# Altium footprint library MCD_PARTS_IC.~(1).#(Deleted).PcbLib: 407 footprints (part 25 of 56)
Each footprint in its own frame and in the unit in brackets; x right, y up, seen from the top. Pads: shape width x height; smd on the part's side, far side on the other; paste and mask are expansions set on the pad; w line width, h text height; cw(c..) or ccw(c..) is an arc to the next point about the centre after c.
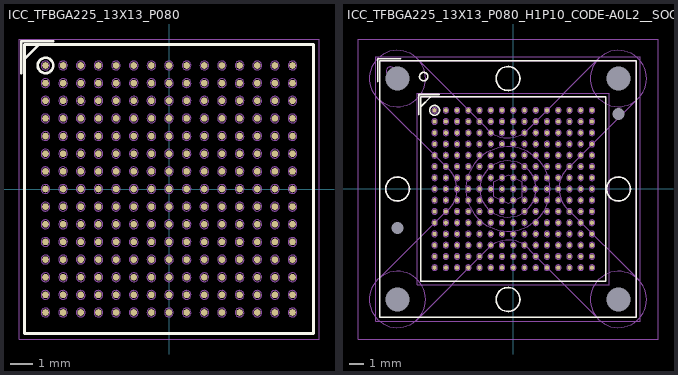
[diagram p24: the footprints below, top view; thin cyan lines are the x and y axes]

## ICC_TFBGA225_13X13_P080 [mm] "MCD-04287"
height 1.2
pads (225):
  round 0.3 smd mask+0.05: A1(-5.6,5.6) A2(-4.8,5.6) A3(-4,5.6) A4(-3.2,5.6) A5(-2.4,5.6) A6(-1.6,5.6) A7(-0.8,5.6) A8(0,5.6) A9(0.8,5.6) A10(1.6,5.6) A11(2.4,5.6) A12(3.2,5.6) A13(4,5.6) A14(4.8,5.6) A15(5.6,5.6) B1(-5.6,4.8) B2(-4.8,4.8) B3(-4,4.8) B4(-3.2,4.8) B5(-2.4,4.8) B6(-1.6,4.8) B7(-0.8,4.8) B8(0,4.8) B9(0.8,4.8) B10(1.6,4.8) B11(2.4,4.8) B12(3.2,4.8) B13(4,4.8) B14(4.8,4.8) B15(5.6,4.8) C1(-5.6,4) C2(-4.8,4) C3(-4,4) C4(-3.2,4) C5(-2.4,4) C6(-1.6,4) C7(-0.8,4) C8(0,4) C9(0.8,4) C10(1.6,4) C11(2.4,4) C12(3.2,4) C13(4,4) C14(4.8,4) C15(5.6,4) D1(-5.6,3.2) D2(-4.8,3.2) D3(-4,3.2) D4(-3.2,3.2) D5(-2.4,3.2) D6(-1.6,3.2) D7(-0.8,3.2) D8(0,3.2) D9(0.8,3.2) D10(1.6,3.2) D11(2.4,3.2) D12(3.2,3.2) D13(4,3.2) D14(4.8,3.2) D15(5.6,3.2) E1(-5.6,2.4) E2(-4.8,2.4) E3(-4,2.4) E4(-3.2,2.4) E5(-2.4,2.4) E6(-1.6,2.4) E7(-0.8,2.4) E8(0,2.4) E9(0.8,2.4) E10(1.6,2.4) E11(2.4,2.4) E12(3.2,2.4) E13(4,2.4) E14(4.8,2.4) E15(5.6,2.4) F1(-5.6,1.6) F2(-4.8,1.6) F3(-4,1.6) F4(-3.2,1.6) F5(-2.4,1.6) F6(-1.6,1.6) F7(-0.8,1.6) F8(0,1.6) F9(0.8,1.6) F10(1.6,1.6) F11(2.4,1.6) F12(3.2,1.6) F13(4,1.6) F14(4.8,1.6) F15(5.6,1.6) G1(-5.6,0.8) G2(-4.8,0.8) G3(-4,0.8) G4(-3.2,0.8) G5(-2.4,0.8) G6(-1.6,0.8) G7(-0.8,0.8) G8(0,0.8) G9(0.8,0.8) G10(1.6,0.8) G11(2.4,0.8) G12(3.2,0.8) G13(4,0.8) G14(4.8,0.8) G15(5.6,0.8) H1(-5.6,0) H2(-4.8,0) H3(-4,0) H4(-3.2,0) H5(-2.4,0) H6(-1.6,0) H7(-0.8,0) H8(0,0) H9(0.8,0) H10(1.6,0) H11(2.4,0) H12(3.2,0) H13(4,0) H14(4.8,0) H15(5.6,0) J1(-5.6,-0.8) J2(-4.8,-0.8) J3(-4,-0.8) J4(-3.2,-0.8) J5(-2.4,-0.8) J6(-1.6,-0.8) J7(-0.8,-0.8) J8(0,-0.8) J9(0.8,-0.8) J10(1.6,-0.8) J11(2.4,-0.8) J12(3.2,-0.8) J13(4,-0.8) J14(4.8,-0.8) J15(5.6,-0.8) K1(-5.6,-1.6) K2(-4.8,-1.6) K3(-4,-1.6) K4(-3.2,-1.6) K5(-2.4,-1.6) K6(-1.6,-1.6) K7(-0.8,-1.6) K8(0,-1.6) K9(0.8,-1.6) K10(1.6,-1.6) K11(2.4,-1.6) K12(3.2,-1.6) K13(4,-1.6) K14(4.8,-1.6) K15(5.6,-1.6) L1(-5.6,-2.4) L2(-4.8,-2.4) L3(-4,-2.4) L4(-3.2,-2.4) L5(-2.4,-2.4) L6(-1.6,-2.4) L7(-0.8,-2.4) L8(0,-2.4) L9(0.8,-2.4) L10(1.6,-2.4) L11(2.4,-2.4) L12(3.2,-2.4) L13(4,-2.4) L14(4.8,-2.4) L15(5.6,-2.4) M1(-5.6,-3.2) M2(-4.8,-3.2) M3(-4,-3.2) M4(-3.2,-3.2) M5(-2.4,-3.2) M6(-1.6,-3.2) M7(-0.8,-3.2) M8(0,-3.2) M9(0.8,-3.2) M10(1.6,-3.2) M11(2.4,-3.2) M12(3.2,-3.2) M13(4,-3.2) M14(4.8,-3.2) M15(5.6,-3.2) N1(-5.6,-4) N2(-4.8,-4) N3(-4,-4) N4(-3.2,-4) N5(-2.4,-4) N6(-1.6,-4) N7(-0.8,-4) N8(0,-4) N9(0.8,-4) N10(1.6,-4) N11(2.4,-4) N12(3.2,-4) N13(4,-4) N14(4.8,-4) N15(5.6,-4) P1(-5.6,-4.8) P2(-4.8,-4.8) P3(-4,-4.8) P4(-3.2,-4.8) P5(-2.4,-4.8) P6(-1.6,-4.8) P7(-0.8,-4.8) P8(0,-4.8) P9(0.8,-4.8) P10(1.6,-4.8) P11(2.4,-4.8) P12(3.2,-4.8) P13(4,-4.8) P14(4.8,-4.8) P15(5.6,-4.8) R1(-5.6,-5.6) R2(-4.8,-5.6) R3(-4,-5.6) R4(-3.2,-5.6) R5(-2.4,-5.6) R6(-1.6,-5.6) R7(-0.8,-5.6) R8(0,-5.6) R9(0.8,-5.6) R10(1.6,-5.6) R11(2.4,-5.6) R12(3.2,-5.6) R13(4,-5.6) R14(4.8,-5.6) R15(5.6,-5.6)
Top Overlay:
  circle w0.12: c-5.6,5.6 r0.35
  lines w0.12: -6.7,5.25 -6.7,6.7 -5.25,6.7 ; -6.55,5.895 -5.895,6.55 ; -6.55,-6.55 6.55,-6.55 6.55,6.55 -6.55,6.55 -6.55,-6.55
M14-Top Assembly:
  drawing of 229 lines, arcs and shapes, not listed
  text "'.Designator'" at 0,0 h0.75
  text "A1" at -5.85,5.425 h0.4
M16-Top Courtyard:
  lines w0.01: -6.8,-6.8 6.8,-6.8 6.8,6.8 -6.8,6.8 -6.8,-6.8
3D body: height 0.36, standoff -0.04, extent 5.401,5.403 5.8,5.797
3D body: height 1.2, standoff 0.3, extent -6.55,-6.55 6.55,6.55
3D body: height 0.36, standoff -0.04, extent 4.601,5.403 5,5.797
3D body: height 0.36, standoff -0.04, extent 3.801,5.403 4.2,5.797
3D body: height 0.36, standoff -0.04, extent 3.001,5.403 3.4,5.797
3D body: height 0.36, standoff -0.04, extent 2.201,5.403 2.6,5.797
3D body: height 0.36, standoff -0.04, extent -1.799,5.403 -1.4,5.797
3D body: height 0.36, standoff -0.04, extent -0.999,5.403 -0.6,5.797
3D body: height 0.36, standoff -0.04, extent -0.199,5.403 0.2,5.797
3D body: height 0.36, standoff -0.04, extent 0.601,5.403 1,5.797
3D body: height 0.36, standoff -0.04, extent 1.401,5.403 1.8,5.797
3D body: height 0.36, standoff -0.04, extent -5.799,5.403 -5.4,5.797
3D body: height 0.36, standoff -0.04, extent -4.999,5.403 -4.6,5.797
3D body: height 0.36, standoff -0.04, extent -4.199,5.403 -3.8,5.797
3D body: height 0.36, standoff -0.04, extent -3.399,5.403 -3,5.797
3D body: height 0.36, standoff -0.04, extent -2.599,5.403 -2.2,5.797
3D body: height 0.36, standoff -0.04, extent -2.599,4.603 -2.2,4.997
3D body: height 0.36, standoff -0.04, extent -3.399,4.603 -3,4.997
3D body: height 0.36, standoff -0.04, extent -4.199,4.603 -3.8,4.997
3D body: height 0.36, standoff -0.04, extent -4.999,4.603 -4.6,4.997
3D body: height 0.36, standoff -0.04, extent -5.799,4.603 -5.4,4.997
3D body: height 0.36, standoff -0.04, extent 1.401,4.603 1.8,4.997
3D body: height 0.36, standoff -0.04, extent 0.601,4.603 1,4.997
3D body: height 0.36, standoff -0.04, extent -0.199,4.603 0.2,4.997
3D body: height 0.36, standoff -0.04, extent -0.999,4.603 -0.6,4.997
3D body: height 0.36, standoff -0.04, extent -1.799,4.603 -1.4,4.997
3D body: height 0.36, standoff -0.04, extent 2.201,4.603 2.6,4.997
3D body: height 0.36, standoff -0.04, extent 3.001,4.603 3.4,4.997
3D body: height 0.36, standoff -0.04, extent 3.801,4.603 4.2,4.997
3D body: height 0.36, standoff -0.04, extent 4.601,4.603 5,4.997
3D body: height 0.36, standoff -0.04, extent 5.401,4.603 5.8,4.997
3D body: height 0.36, standoff -0.04, extent -2.599,3.803 -2.2,4.197
3D body: height 0.36, standoff -0.04, extent -3.399,3.803 -3,4.197
3D body: height 0.36, standoff -0.04, extent -4.199,3.803 -3.8,4.197
3D body: height 0.36, standoff -0.04, extent -4.999,3.803 -4.6,4.197
3D body: height 0.36, standoff -0.04, extent -5.799,3.803 -5.4,4.197
3D body: height 0.36, standoff -0.04, extent 1.401,3.803 1.8,4.197
3D body: height 0.36, standoff -0.04, extent 0.601,3.803 1,4.197
3D body: height 0.36, standoff -0.04, extent -0.199,3.803 0.2,4.197
3D body: height 0.36, standoff -0.04, extent -0.999,3.803 -0.6,4.197
3D body: height 0.36, standoff -0.04, extent -1.799,3.803 -1.4,4.197
3D body: height 0.36, standoff -0.04, extent 2.201,3.803 2.6,4.197
3D body: height 0.36, standoff -0.04, extent 3.001,3.803 3.4,4.197
3D body: height 0.36, standoff -0.04, extent 3.801,3.803 4.2,4.197
3D body: height 0.36, standoff -0.04, extent 4.601,3.803 5,4.197
3D body: height 0.36, standoff -0.04, extent 5.401,3.803 5.8,4.197
3D body: height 0.36, standoff -0.04, extent -2.599,3.003 -2.2,3.397
3D body: height 0.36, standoff -0.04, extent -3.399,3.003 -3,3.397
3D body: height 0.36, standoff -0.04, extent -4.199,3.003 -3.8,3.397
3D body: height 0.36, standoff -0.04, extent -4.999,3.003 -4.6,3.397
3D body: height 0.36, standoff -0.04, extent -5.799,3.003 -5.4,3.397
3D body: height 0.36, standoff -0.04, extent 1.401,3.003 1.8,3.397
3D body: height 0.36, standoff -0.04, extent 0.601,3.003 1,3.397
3D body: height 0.36, standoff -0.04, extent -0.199,3.003 0.2,3.397
3D body: height 0.36, standoff -0.04, extent -0.999,3.003 -0.6,3.397
3D body: height 0.36, standoff -0.04, extent -1.799,3.003 -1.4,3.397
3D body: height 0.36, standoff -0.04, extent 2.201,3.003 2.6,3.397
3D body: height 0.36, standoff -0.04, extent 3.001,3.003 3.4,3.397
3D body: height 0.36, standoff -0.04, extent 3.801,3.003 4.2,3.397
3D body: height 0.36, standoff -0.04, extent 4.601,3.003 5,3.397
3D body: height 0.36, standoff -0.04, extent 5.401,3.003 5.8,3.397
3D body: height 0.36, standoff -0.04, extent -2.599,2.203 -2.2,2.597
3D body: height 0.36, standoff -0.04, extent -3.399,2.203 -3,2.597
3D body: height 0.36, standoff -0.04, extent -4.199,2.203 -3.8,2.597
3D body: height 0.36, standoff -0.04, extent -4.999,2.203 -4.6,2.597
3D body: height 0.36, standoff -0.04, extent -5.799,2.203 -5.4,2.597
3D body: height 0.36, standoff -0.04, extent 1.401,2.203 1.8,2.597
3D body: height 0.36, standoff -0.04, extent 0.601,2.203 1,2.597
3D body: height 0.36, standoff -0.04, extent -0.199,2.203 0.2,2.597
3D body: height 0.36, standoff -0.04, extent -0.999,2.203 -0.6,2.597
3D body: height 0.36, standoff -0.04, extent -1.799,2.203 -1.4,2.597
3D body: height 0.36, standoff -0.04, extent 2.201,2.203 2.6,2.597
3D body: height 0.36, standoff -0.04, extent 3.001,2.203 3.4,2.597
3D body: height 0.36, standoff -0.04, extent 3.801,2.203 4.2,2.597
3D body: height 0.36, standoff -0.04, extent 4.601,2.203 5,2.597
3D body: height 0.36, standoff -0.04, extent 5.401,2.203 5.8,2.597
3D body: height 0.36, standoff -0.04, extent -2.599,1.403 -2.2,1.797
3D body: height 0.36, standoff -0.04, extent -3.399,1.403 -3,1.797
3D body: height 0.36, standoff -0.04, extent -4.199,1.403 -3.8,1.797
3D body: height 0.36, standoff -0.04, extent -4.999,1.403 -4.6,1.797
3D body: height 0.36, standoff -0.04, extent -5.799,1.403 -5.4,1.797
3D body: height 0.36, standoff -0.04, extent 1.401,1.403 1.8,1.797
3D body: height 0.36, standoff -0.04, extent 0.601,1.403 1,1.797
3D body: height 0.36, standoff -0.04, extent -0.199,1.403 0.2,1.797
3D body: height 0.36, standoff -0.04, extent -0.999,1.403 -0.6,1.797
3D body: height 0.36, standoff -0.04, extent -1.799,1.403 -1.4,1.797
3D body: height 0.36, standoff -0.04, extent 2.201,1.403 2.6,1.797
3D body: height 0.36, standoff -0.04, extent 3.001,1.403 3.4,1.797
3D body: height 0.36, standoff -0.04, extent 3.801,1.403 4.2,1.797
3D body: height 0.36, standoff -0.04, extent 4.601,1.403 5,1.797
3D body: height 0.36, standoff -0.04, extent 5.401,1.403 5.8,1.797
3D body: height 0.36, standoff -0.04, extent -2.599,0.603 -2.2,0.997
3D body: height 0.36, standoff -0.04, extent -3.399,0.603 -3,0.997
3D body: height 0.36, standoff -0.04, extent -4.199,0.603 -3.8,0.997
3D body: height 0.36, standoff -0.04, extent -4.999,0.603 -4.6,0.997
3D body: height 0.36, standoff -0.04, extent -5.799,0.603 -5.4,0.997
3D body: height 0.36, standoff -0.04, extent 1.401,0.603 1.8,0.997
3D body: height 0.36, standoff -0.04, extent 0.601,0.603 1,0.997
3D body: height 0.36, standoff -0.04, extent -0.199,0.603 0.2,0.997
3D body: height 0.36, standoff -0.04, extent -0.999,0.603 -0.6,0.997
3D body: height 0.36, standoff -0.04, extent -1.799,0.603 -1.4,0.997
3D body: height 0.36, standoff -0.04, extent 2.201,0.603 2.6,0.997
3D body: height 0.36, standoff -0.04, extent 3.001,0.603 3.4,0.997
3D body: height 0.36, standoff -0.04, extent 3.801,0.603 4.2,0.997
3D body: height 0.36, standoff -0.04, extent 4.601,0.603 5,0.997
3D body: height 0.36, standoff -0.04, extent 5.401,0.603 5.8,0.997
3D body: height 0.36, standoff -0.04, extent -2.599,-0.197 -2.2,0.197
3D body: height 0.36, standoff -0.04, extent -3.399,-0.197 -3,0.197
3D body: height 0.36, standoff -0.04, extent -4.199,-0.197 -3.8,0.197
3D body: height 0.36, standoff -0.04, extent -4.999,-0.197 -4.6,0.197
3D body: height 0.36, standoff -0.04, extent -5.799,-0.197 -5.4,0.197
3D body: height 0.36, standoff -0.04, extent 1.401,-0.197 1.8,0.197
3D body: height 0.36, standoff -0.04, extent 0.601,-0.197 1,0.197
3D body: height 0.36, standoff -0.04, extent -0.199,-0.197 0.2,0.197
3D body: height 0.36, standoff -0.04, extent -0.999,-0.197 -0.6,0.197
3D body: height 0.36, standoff -0.04, extent -1.799,-0.197 -1.4,0.197
3D body: height 0.36, standoff -0.04, extent 2.201,-0.197 2.6,0.197
3D body: height 0.36, standoff -0.04, extent 3.001,-0.197 3.4,0.197
3D body: height 0.36, standoff -0.04, extent 3.801,-0.197 4.2,0.197
3D body: height 0.36, standoff -0.04, extent 4.601,-0.197 5,0.197
3D body: height 0.36, standoff -0.04, extent 5.401,-0.197 5.8,0.197
3D body: height 0.36, standoff -0.04, extent -2.599,-0.997 -2.2,-0.603
3D body: height 0.36, standoff -0.04, extent -3.399,-0.997 -3,-0.603
3D body: height 0.36, standoff -0.04, extent -4.199,-0.997 -3.8,-0.603
3D body: height 0.36, standoff -0.04, extent -4.999,-0.997 -4.6,-0.603
3D body: height 0.36, standoff -0.04, extent -5.799,-0.997 -5.4,-0.603
3D body: height 0.36, standoff -0.04, extent 1.401,-0.997 1.8,-0.603
3D body: height 0.36, standoff -0.04, extent 0.601,-0.997 1,-0.603
3D body: height 0.36, standoff -0.04, extent -0.199,-0.997 0.2,-0.603
3D body: height 0.36, standoff -0.04, extent -0.999,-0.997 -0.6,-0.603
3D body: height 0.36, standoff -0.04, extent -1.799,-0.997 -1.4,-0.603
3D body: height 0.36, standoff -0.04, extent 2.201,-0.997 2.6,-0.603
3D body: height 0.36, standoff -0.04, extent 3.001,-0.997 3.4,-0.603
3D body: height 0.36, standoff -0.04, extent 3.801,-0.997 4.2,-0.603
3D body: height 0.36, standoff -0.04, extent 4.601,-0.997 5,-0.603
3D body: height 0.36, standoff -0.04, extent 5.401,-0.997 5.8,-0.603
3D body: height 0.36, standoff -0.04, extent -2.599,-1.797 -2.2,-1.403
3D body: height 0.36, standoff -0.04, extent -3.399,-1.797 -3,-1.403
3D body: height 0.36, standoff -0.04, extent -4.199,-1.797 -3.8,-1.403
3D body: height 0.36, standoff -0.04, extent -4.999,-1.797 -4.6,-1.403
3D body: height 0.36, standoff -0.04, extent -5.799,-1.797 -5.4,-1.403
3D body: height 0.36, standoff -0.04, extent 1.401,-1.797 1.8,-1.403
3D body: height 0.36, standoff -0.04, extent 0.601,-1.797 1,-1.403
3D body: height 0.36, standoff -0.04, extent -0.199,-1.797 0.2,-1.403
3D body: height 0.36, standoff -0.04, extent -0.999,-1.797 -0.6,-1.403
3D body: height 0.36, standoff -0.04, extent -1.799,-1.797 -1.4,-1.403
3D body: height 0.36, standoff -0.04, extent 2.201,-1.797 2.6,-1.403
3D body: height 0.36, standoff -0.04, extent 3.001,-1.797 3.4,-1.403
3D body: height 0.36, standoff -0.04, extent 3.801,-1.797 4.2,-1.403
3D body: height 0.36, standoff -0.04, extent 4.601,-1.797 5,-1.403
3D body: height 0.36, standoff -0.04, extent 5.401,-1.797 5.8,-1.403
3D body: height 0.36, standoff -0.04, extent -2.599,-2.597 -2.2,-2.203
3D body: height 0.36, standoff -0.04, extent -3.399,-2.597 -3,-2.203
3D body: height 0.36, standoff -0.04, extent -4.199,-2.597 -3.8,-2.203
3D body: height 0.36, standoff -0.04, extent -4.999,-2.597 -4.6,-2.203
3D body: height 0.36, standoff -0.04, extent -5.799,-2.597 -5.4,-2.203
3D body: height 0.36, standoff -0.04, extent 1.401,-2.597 1.8,-2.203
3D body: height 0.36, standoff -0.04, extent 0.601,-2.597 1,-2.203
3D body: height 0.36, standoff -0.04, extent -0.199,-2.597 0.2,-2.203
3D body: height 0.36, standoff -0.04, extent -0.999,-2.597 -0.6,-2.203
3D body: height 0.36, standoff -0.04, extent -1.799,-2.597 -1.4,-2.203
3D body: height 0.36, standoff -0.04, extent 2.201,-2.597 2.6,-2.203
3D body: height 0.36, standoff -0.04, extent 3.001,-2.597 3.4,-2.203
3D body: height 0.36, standoff -0.04, extent 3.801,-2.597 4.2,-2.203
3D body: height 0.36, standoff -0.04, extent 4.601,-2.597 5,-2.203
3D body: height 0.36, standoff -0.04, extent 5.401,-2.597 5.8,-2.203
3D body: height 0.36, standoff -0.04, extent -2.599,-3.397 -2.2,-3.003
3D body: height 0.36, standoff -0.04, extent -3.399,-3.397 -3,-3.003
3D body: height 0.36, standoff -0.04, extent -4.199,-3.397 -3.8,-3.003
3D body: height 0.36, standoff -0.04, extent -4.999,-3.397 -4.6,-3.003
3D body: height 0.36, standoff -0.04, extent -5.799,-3.397 -5.4,-3.003
3D body: height 0.36, standoff -0.04, extent 1.401,-3.397 1.8,-3.003
3D body: height 0.36, standoff -0.04, extent 0.601,-3.397 1,-3.003
3D body: height 0.36, standoff -0.04, extent -0.199,-3.397 0.2,-3.003
3D body: height 0.36, standoff -0.04, extent -0.999,-3.397 -0.6,-3.003
3D body: height 0.36, standoff -0.04, extent -1.799,-3.397 -1.4,-3.003
3D body: height 0.36, standoff -0.04, extent 2.201,-3.397 2.6,-3.003
3D body: height 0.36, standoff -0.04, extent 3.001,-3.397 3.4,-3.003
3D body: height 0.36, standoff -0.04, extent 3.801,-3.397 4.2,-3.003
3D body: height 0.36, standoff -0.04, extent 4.601,-3.397 5,-3.003
3D body: height 0.36, standoff -0.04, extent 5.401,-3.397 5.8,-3.003
3D body: height 0.36, standoff -0.04, extent -2.599,-4.197 -2.2,-3.803
3D body: height 0.36, standoff -0.04, extent -3.399,-4.197 -3,-3.803
3D body: height 0.36, standoff -0.04, extent -4.199,-4.197 -3.8,-3.803
3D body: height 0.36, standoff -0.04, extent -4.999,-4.197 -4.6,-3.803
3D body: height 0.36, standoff -0.04, extent -5.799,-4.197 -5.4,-3.803
3D body: height 0.36, standoff -0.04, extent 1.401,-4.197 1.8,-3.803
3D body: height 0.36, standoff -0.04, extent 0.601,-4.197 1,-3.803
3D body: height 0.36, standoff -0.04, extent -0.199,-4.197 0.2,-3.803
3D body: height 0.36, standoff -0.04, extent -0.999,-4.197 -0.6,-3.803
3D body: height 0.36, standoff -0.04, extent -1.799,-4.197 -1.4,-3.803
3D body: height 0.36, standoff -0.04, extent 2.201,-4.197 2.6,-3.803
3D body: height 0.36, standoff -0.04, extent 3.001,-4.197 3.4,-3.803
3D body: height 0.36, standoff -0.04, extent 3.801,-4.197 4.2,-3.803
3D body: height 0.36, standoff -0.04, extent 4.601,-4.197 5,-3.803
3D body: height 0.36, standoff -0.04, extent 5.401,-4.197 5.8,-3.803
3D body: height 0.36, standoff -0.04, extent -2.599,-4.997 -2.2,-4.603
3D body: height 0.36, standoff -0.04, extent -3.399,-4.997 -3,-4.603
3D body: height 0.36, standoff -0.04, extent -4.199,-4.997 -3.8,-4.603
3D body: height 0.36, standoff -0.04, extent -4.999,-4.997 -4.6,-4.603
3D body: height 0.36, standoff -0.04, extent -5.799,-4.997 -5.4,-4.603
3D body: height 0.36, standoff -0.04, extent 1.401,-4.997 1.8,-4.603
3D body: height 0.36, standoff -0.04, extent 0.601,-4.997 1,-4.603
3D body: height 0.36, standoff -0.04, extent -0.199,-4.997 0.2,-4.603
3D body: height 0.36, standoff -0.04, extent -0.999,-4.997 -0.6,-4.603
3D body: height 0.36, standoff -0.04, extent -1.799,-4.997 -1.4,-4.603
3D body: height 0.36, standoff -0.04, extent 2.201,-4.997 2.6,-4.603
3D body: height 0.36, standoff -0.04, extent 3.001,-4.997 3.4,-4.603
3D body: height 0.36, standoff -0.04, extent 3.801,-4.997 4.2,-4.603
3D body: height 0.36, standoff -0.04, extent 4.601,-4.997 5,-4.603
3D body: height 0.36, standoff -0.04, extent 5.401,-4.997 5.8,-4.603
3D body: height 0.36, standoff -0.04, extent -2.599,-5.797 -2.2,-5.403
3D body: height 0.36, standoff -0.04, extent -3.399,-5.797 -3,-5.403
3D body: height 0.36, standoff -0.04, extent -4.199,-5.797 -3.8,-5.403
3D body: height 0.36, standoff -0.04, extent -4.999,-5.797 -4.6,-5.403
3D body: height 0.36, standoff -0.04, extent -5.799,-5.797 -5.4,-5.403
3D body: height 0.36, standoff -0.04, extent 1.401,-5.797 1.8,-5.403
3D body: height 0.36, standoff -0.04, extent 0.601,-5.797 1,-5.403
3D body: height 0.36, standoff -0.04, extent -0.199,-5.797 0.2,-5.403
3D body: height 0.36, standoff -0.04, extent -0.999,-5.797 -0.6,-5.403
3D body: height 0.36, standoff -0.04, extent -1.799,-5.797 -1.4,-5.403
3D body: height 0.36, standoff -0.04, extent 2.201,-5.797 2.6,-5.403
3D body: height 0.36, standoff -0.04, extent 3.001,-5.797 3.4,-5.403
3D body: height 0.36, standoff -0.04, extent 3.801,-5.797 4.2,-5.403
3D body: height 0.36, standoff -0.04, extent 4.601,-5.797 5,-5.403
3D body: height 0.36, standoff -0.04, extent 5.401,-5.797 5.8,-5.403
3D body: height 1.21, standoff 1.2, extent -5.898,5.301 -5.3,5.9

## ICC_TFBGA225_13X13_P080_H1P10_CODE-A0L2__SOCKET_IRONWOOD_CS1222291-D6524MF [mm] "MCD-04287"
height 8.25
pads (231):
  round 0.3 smd mask+0.05: A1(-5.6,5.6) A2(-4.8,5.6) A3(-4,5.6) A4(-3.2,5.6) A5(-2.4,5.6) A6(-1.6,5.6) A7(-0.8,5.6) A8(0,5.6) A9(0.8,5.6) A10(1.6,5.6) A11(2.4,5.6) A12(3.2,5.6) A13(4,5.6) A14(4.8,5.6) A15(5.6,5.6) B1(-5.6,4.8) B2(-4.8,4.8) B3(-4,4.8) B4(-3.2,4.8) B5(-2.4,4.8) B6(-1.6,4.8) B7(-0.8,4.8) B8(0,4.8) B9(0.8,4.8) B10(1.6,4.8) B11(2.4,4.8) B12(3.2,4.8) B13(4,4.8) B14(4.8,4.8) B15(5.6,4.8) C1(-5.6,4) C2(-4.8,4) C3(-4,4) C4(-3.2,4) C5(-2.4,4) C6(-1.6,4) C7(-0.8,4) C8(0,4) C9(0.8,4) C10(1.6,4) C11(2.4,4) C12(3.2,4) C13(4,4) C14(4.8,4) C15(5.6,4) D1(-5.6,3.2) D2(-4.8,3.2) D3(-4,3.2) D4(-3.2,3.2) D5(-2.4,3.2) D6(-1.6,3.2) D7(-0.8,3.2) D8(0,3.2) D9(0.8,3.2) D10(1.6,3.2) D11(2.4,3.2) D12(3.2,3.2) D13(4,3.2) D14(4.8,3.2) D15(5.6,3.2) E1(-5.6,2.4) E2(-4.8,2.4) E3(-4,2.4) E4(-3.2,2.4) E5(-2.4,2.4) E6(-1.6,2.4) E7(-0.8,2.4) E8(0,2.4) E9(0.8,2.4) E10(1.6,2.4) E11(2.4,2.4) E12(3.2,2.4) E13(4,2.4) E14(4.8,2.4) E15(5.6,2.4) F1(-5.6,1.6) F2(-4.8,1.6) F3(-4,1.6) F4(-3.2,1.6) F5(-2.4,1.6) F6(-1.6,1.6) F7(-0.8,1.6) F8(0,1.6) F9(0.8,1.6) F10(1.6,1.6) F11(2.4,1.6) F12(3.2,1.6) F13(4,1.6) F14(4.8,1.6) F15(5.6,1.6) G1(-5.6,0.8) G2(-4.8,0.8) G3(-4,0.8) G4(-3.2,0.8) G5(-2.4,0.8) G6(-1.6,0.8) G7(-0.8,0.8) G8(0,0.8) G9(0.8,0.8) G10(1.6,0.8) G11(2.4,0.8) G12(3.2,0.8) G13(4,0.8) G14(4.8,0.8) G15(5.6,0.8) H1(-5.6,0) H2(-4.8,0) H3(-4,0) H4(-3.2,0) H5(-2.4,0) H6(-1.6,0) H7(-0.8,0) H8(0,0) H9(0.8,0) H10(1.6,0) H11(2.4,0) H12(3.2,0) H13(4,0) H14(4.8,0) H15(5.6,0) J1(-5.6,-0.8) J2(-4.8,-0.8) J3(-4,-0.8) J4(-3.2,-0.8) J5(-2.4,-0.8) J6(-1.6,-0.8) J7(-0.8,-0.8) J8(0,-0.8) J9(0.8,-0.8) J10(1.6,-0.8) J11(2.4,-0.8) J12(3.2,-0.8) J13(4,-0.8) J14(4.8,-0.8) J15(5.6,-0.8) K1(-5.6,-1.6) K2(-4.8,-1.6) K3(-4,-1.6) K4(-3.2,-1.6) K5(-2.4,-1.6) K6(-1.6,-1.6) K7(-0.8,-1.6) K8(0,-1.6) K9(0.8,-1.6) K10(1.6,-1.6) K11(2.4,-1.6) K12(3.2,-1.6) K13(4,-1.6) K14(4.8,-1.6) K15(5.6,-1.6) L1(-5.6,-2.4) L2(-4.8,-2.4) L3(-4,-2.4) L4(-3.2,-2.4) L5(-2.4,-2.4) L6(-1.6,-2.4) L7(-0.8,-2.4) L8(0,-2.4) L9(0.8,-2.4) L10(1.6,-2.4) L11(2.4,-2.4) L12(3.2,-2.4) L13(4,-2.4) L14(4.8,-2.4) L15(5.6,-2.4) M1(-5.6,-3.2) M2(-4.8,-3.2) M3(-4,-3.2) M4(-3.2,-3.2) M5(-2.4,-3.2) M6(-1.6,-3.2) M7(-0.8,-3.2) M8(0,-3.2) M9(0.8,-3.2) M10(1.6,-3.2) M11(2.4,-3.2) M12(3.2,-3.2) M13(4,-3.2) M14(4.8,-3.2) M15(5.6,-3.2) N1(-5.6,-4) N2(-4.8,-4) N3(-4,-4) N4(-3.2,-4) N5(-2.4,-4) N6(-1.6,-4) N7(-0.8,-4) N8(0,-4) N9(0.8,-4) N10(1.6,-4) N11(2.4,-4) N12(3.2,-4) N13(4,-4) N14(4.8,-4) N15(5.6,-4) P1(-5.6,-4.8) P2(-4.8,-4.8) P3(-4,-4.8) P4(-3.2,-4.8) P5(-2.4,-4.8) P6(-1.6,-4.8) P7(-0.8,-4.8) P8(0,-4.8) P9(0.8,-4.8) P10(1.6,-4.8) P11(2.4,-4.8) P12(3.2,-4.8) P13(4,-4.8) P14(4.8,-4.8) P15(5.6,-4.8) R1(-5.6,-5.6) R2(-4.8,-5.6) R3(-4,-5.6) R4(-3.2,-5.6) R5(-2.4,-5.6) R6(-1.6,-5.6) R7(-0.8,-5.6) R8(0,-5.6) R9(0.8,-5.6) R10(1.6,-5.6) R11(2.4,-5.6) R12(3.2,-5.6) R13(4,-5.6) R14(4.8,-5.6) R15(5.6,-5.6)
  round 0 hole 0.85 unplated mask+0.05: NPTH1(7.487,5.322) NPTH2(-8.238,-2.783)
  round 0 hole 1.71 unplated mask+0.05: PTH1(-8.238,7.862) PTH2(7.487,7.862) PTH3(7.487,-7.863) PTH4(-8.238,-7.863)
Top Overlay:
  circle w0.12: c-5.6,5.6 r0.35
  circle w0.12: c-8.238,0 r0.85
  circle w0.12: c-0.375,7.862 r0.85
  circle w0.12: c7.487,0 r0.85
  circle w0.12: c-0.375,-7.863 r0.85
  circle w0.12: c-6.375,8 r0.3
  lines w0.12: -9.65,7.625 -9.65,9.275 -8,9.275 ; -6.725,5.275 -6.725,6.725 -5.275,6.725 ; -6.55,5.895 -5.895,6.55 ; -9.5,-9.125 -9.5,9.125 8.75,9.125 8.75,-9.125 -9.5,-9.125 ; -6.575,-6.575 6.575,-6.575 6.575,6.575 -6.575,6.575 -6.575,-6.575
Bottom Overlay:
  lines w0.12: -10.75,-10.375 -10.75,10.375 -7.625,10.375 10,10.375 10,-10.375 -10.75,-10.375
M8-Bottom Info:
  circle w0.01: c-0.375,0 r2
  circle w0.01: c-8.238,7.862 r2
  circle w0.01: c7.487,7.862 r2
  circle w0.01: c7.487,-7.863 r2
  circle w0.01: c-8.238,-7.863 r2
  lines w0.01: -9.744,6.544 -4.624,1.424 ; -9.494,-6.319 -4.7,-1.525 ; -6.919,-9.369 -1.799,-4.249 ; -6.694,9.119 -1.9,4.325 ; -4.695,-1.531 ccw(c-6.015,-0.015) -4.618,1.43 ; -1.906,4.32 ccw(c-0.39,5.64) 1.055,4.243 ; -1.805,-4.243 cw(c-0.36,-5.64) 1.156,-4.32 ; 1.049,4.249 6.169,9.369 ; 1.15,-4.325 5.944,-9.119 ; 3.868,-1.43 cw(c5.265,0.015) 3.945,1.531 ; 3.874,-1.424 8.994,-6.544 ; 3.95,1.525 8.744,6.319
  text "1.4mm" at -2.11,-3.14 h1.5
  text "Max Height :" at -3.45,2.18 h1.5
M14-Top Assembly:
  drawing of 245 lines, arcs and shapes, not listed
  text "'.Designator'" at 0,0 h0.75
  text "A1" at -5.85,5.425 h0.4
M15-Bottom Assembly:
  circle w0.01: c-8.238,-7.863 r2
  circle w0.01: c7.487,-7.863 r2
  circle w0.01: c7.487,7.862 r2
  circle w0.01: c-8.238,7.862 r2
  circle w0.01: c-0.375,0 r2
  lines w0.01: -9.744,6.544 -4.624,1.424 ; -9.494,-6.319 -4.7,-1.525 ; -6.919,-9.369 -1.799,-4.249 ; -6.694,9.119 -1.9,4.325 ; -4.695,-1.531 ccw(c-6.015,-0.015) -4.618,1.43 ; -1.906,4.32 ccw(c-0.39,5.64) 1.055,4.243 ; -1.805,-4.243 cw(c-0.36,-5.64) 1.156,-4.32 ; 1.049,4.249 6.169,9.369 ; 1.15,-4.325 5.944,-9.119 ; 3.868,-1.43 cw(c5.265,0.015) 3.945,1.531 ; 3.874,-1.424 8.994,-6.544 ; 3.95,1.525 8.744,6.319
M16-Top Courtyard:
  lines w0.01: -9.8,-9.425 9.05,-9.425 9.05,9.425 -9.8,9.425 -9.8,8.5 -9.8,-9.425 ; -6.825,-6.825 6.825,-6.825 6.825,6.825 -6.825,6.825 -6.825,-6.825
M17-Bottom Courtyard:
  lines w0.01: -11.05,-10.675 -11.05,10.675 10.3,10.675 10.3,-10.675 -11.05,-10.675
3D body: height 0.36, standoff -0.04, extent 0.601,-0.997 1,-0.603
3D body: height 0.36, standoff -0.04, extent -0.199,-0.997 0.2,-0.603
3D body: height 0.36, standoff -0.04, extent -0.999,-0.997 -0.6,-0.603
3D body: height 0.36, standoff -0.04, extent -0.999,-0.197 -0.6,0.197
3D body: height 0.36, standoff -0.04, extent -0.199,-0.197 0.2,0.197
3D body: height 0.36, standoff -0.04, extent 0.601,-0.197 1,0.197
3D body: height 0.36, standoff -0.04, extent 0.601,0.603 1,0.997
3D body: height 0.36, standoff -0.04, extent -0.199,0.603 0.2,0.997
3D body: height 0.36, standoff -0.04, extent -0.999,0.603 -0.6,0.997
3D body: height 6, standoff 5, extent -9.081,-0.848 -7.387,0.849
3D body: height 6, standoff 5, extent -1.218,7.014 0.475,8.711
3D body: height 6, standoff 5, extent 6.644,-0.848 8.338,0.849
3D body: height 6, standoff 5, extent -1.218,-8.711 0.475,-7.014
3D body: height 8.25, standoff 5, extent -3.375,-3 2.625,3
3D body: height 5, standoff 0, extent -9.487,-9.112 8.738,9.113
3D body: height 8.26, standoff 8.25, extent -1.375,-1 0.625,1
3D body: height 1.11, standoff 1.1, extent -5.897,5.301 -5.3,5.9
3D body: height 0.36, standoff -0.04, extent 5.401,-5.797 5.8,-5.403
3D body: height 0.36, standoff -0.04, extent 4.601,-5.797 5,-5.403
3D body: height 0.36, standoff -0.04, extent 3.801,-5.797 4.2,-5.403
3D body: height 0.36, standoff -0.04, extent 3.001,-5.797 3.4,-5.403
3D body: height 0.36, standoff -0.04, extent 2.201,-5.797 2.6,-5.403
3D body: height 0.36, standoff -0.04, extent -1.799,-5.797 -1.4,-5.403
3D body: height 0.36, standoff -0.04, extent -0.999,-5.797 -0.6,-5.403
3D body: height 0.36, standoff -0.04, extent -0.199,-5.797 0.2,-5.403
3D body: height 0.36, standoff -0.04, extent 0.601,-5.797 1,-5.403
3D body: height 0.36, standoff -0.04, extent 1.401,-5.797 1.8,-5.403
3D body: height 0.36, standoff -0.04, extent -5.799,-5.797 -5.4,-5.403
3D body: height 0.36, standoff -0.04, extent -4.999,-5.797 -4.6,-5.403
3D body: height 0.36, standoff -0.04, extent -4.199,-5.797 -3.8,-5.403
3D body: height 0.36, standoff -0.04, extent -3.399,-5.797 -3,-5.403
3D body: height 0.36, standoff -0.04, extent -2.599,-5.797 -2.2,-5.403
3D body: height 0.36, standoff -0.04, extent 5.401,-4.997 5.8,-4.603
3D body: height 0.36, standoff -0.04, extent 4.601,-4.997 5,-4.603
3D body: height 0.36, standoff -0.04, extent 3.801,-4.997 4.2,-4.603
3D body: height 0.36, standoff -0.04, extent 3.001,-4.997 3.4,-4.603
3D body: height 0.36, standoff -0.04, extent 2.201,-4.997 2.6,-4.603
3D body: height 0.36, standoff -0.04, extent -1.799,-4.997 -1.4,-4.603
3D body: height 0.36, standoff -0.04, extent -0.999,-4.997 -0.6,-4.603
3D body: height 0.36, standoff -0.04, extent -0.199,-4.997 0.2,-4.603
3D body: height 0.36, standoff -0.04, extent 0.601,-4.997 1,-4.603
3D body: height 0.36, standoff -0.04, extent 1.401,-4.997 1.8,-4.603
3D body: height 0.36, standoff -0.04, extent -5.799,-4.997 -5.4,-4.603
3D body: height 0.36, standoff -0.04, extent -4.999,-4.997 -4.6,-4.603
3D body: height 0.36, standoff -0.04, extent -4.199,-4.997 -3.8,-4.603
3D body: height 0.36, standoff -0.04, extent -3.399,-4.997 -3,-4.603
3D body: height 0.36, standoff -0.04, extent -2.599,-4.997 -2.2,-4.603
3D body: height 0.36, standoff -0.04, extent 5.401,-4.197 5.8,-3.803
3D body: height 0.36, standoff -0.04, extent 4.601,-4.197 5,-3.803
3D body: height 0.36, standoff -0.04, extent 3.801,-4.197 4.2,-3.803
3D body: height 0.36, standoff -0.04, extent 3.001,-4.197 3.4,-3.803
3D body: height 0.36, standoff -0.04, extent 2.201,-4.197 2.6,-3.803
3D body: height 0.36, standoff -0.04, extent -1.799,-4.197 -1.4,-3.803
3D body: height 0.36, standoff -0.04, extent -0.999,-4.197 -0.6,-3.803
3D body: height 0.36, standoff -0.04, extent -0.199,-4.197 0.2,-3.803
3D body: height 0.36, standoff -0.04, extent 0.601,-4.197 1,-3.803
3D body: height 0.36, standoff -0.04, extent 1.401,-4.197 1.8,-3.803
3D body: height 0.36, standoff -0.04, extent -5.799,-4.197 -5.4,-3.803
3D body: height 0.36, standoff -0.04, extent -4.999,-4.197 -4.6,-3.803
3D body: height 0.36, standoff -0.04, extent -4.199,-4.197 -3.8,-3.803
3D body: height 0.36, standoff -0.04, extent -3.399,-4.197 -3,-3.803
3D body: height 0.36, standoff -0.04, extent -2.599,-4.197 -2.2,-3.803
3D body: height 0.36, standoff -0.04, extent 5.401,-3.397 5.8,-3.003
3D body: height 0.36, standoff -0.04, extent 4.601,-3.397 5,-3.003
3D body: height 0.36, standoff -0.04, extent 3.801,-3.397 4.2,-3.003
3D body: height 0.36, standoff -0.04, extent 3.001,-3.397 3.4,-3.003
3D body: height 0.36, standoff -0.04, extent 2.201,-3.397 2.6,-3.003
3D body: height 0.36, standoff -0.04, extent -1.799,-3.397 -1.4,-3.003
3D body: height 0.36, standoff -0.04, extent -0.999,-3.397 -0.6,-3.003
3D body: height 0.36, standoff -0.04, extent -0.199,-3.397 0.2,-3.003
3D body: height 0.36, standoff -0.04, extent 0.601,-3.397 1,-3.003
3D body: height 0.36, standoff -0.04, extent 1.401,-3.397 1.8,-3.003
3D body: height 0.36, standoff -0.04, extent -5.799,-3.397 -5.4,-3.003
3D body: height 0.36, standoff -0.04, extent -4.999,-3.397 -4.6,-3.003
3D body: height 0.36, standoff -0.04, extent -4.199,-3.397 -3.8,-3.003
3D body: height 0.36, standoff -0.04, extent -3.399,-3.397 -3,-3.003
3D body: height 0.36, standoff -0.04, extent -2.599,-3.397 -2.2,-3.003
3D body: height 0.36, standoff -0.04, extent 5.401,-2.597 5.8,-2.203
3D body: height 0.36, standoff -0.04, extent 4.601,-2.597 5,-2.203
3D body: height 0.36, standoff -0.04, extent 3.801,-2.597 4.2,-2.203
3D body: height 0.36, standoff -0.04, extent 3.001,-2.597 3.4,-2.203
3D body: height 0.36, standoff -0.04, extent 2.201,-2.597 2.6,-2.203
3D body: height 0.36, standoff -0.04, extent -1.799,-2.597 -1.4,-2.203
3D body: height 0.36, standoff -0.04, extent -0.999,-2.597 -0.6,-2.203
3D body: height 0.36, standoff -0.04, extent -0.199,-2.597 0.2,-2.203
3D body: height 0.36, standoff -0.04, extent 0.601,-2.597 1,-2.203
3D body: height 0.36, standoff -0.04, extent 1.401,-2.597 1.8,-2.203
3D body: height 0.36, standoff -0.04, extent -5.799,-2.597 -5.4,-2.203
3D body: height 0.36, standoff -0.04, extent -4.999,-2.597 -4.6,-2.203
3D body: height 0.36, standoff -0.04, extent -4.199,-2.597 -3.8,-2.203
3D body: height 0.36, standoff -0.04, extent -3.399,-2.597 -3,-2.203
3D body: height 0.36, standoff -0.04, extent -2.599,-2.597 -2.2,-2.203
3D body: height 0.36, standoff -0.04, extent 5.401,-1.797 5.8,-1.403
3D body: height 0.36, standoff -0.04, extent 4.601,-1.797 5,-1.403
3D body: height 0.36, standoff -0.04, extent 3.801,-1.797 4.2,-1.403
3D body: height 0.36, standoff -0.04, extent 3.001,-1.797 3.4,-1.403
3D body: height 0.36, standoff -0.04, extent 2.201,-1.797 2.6,-1.403
3D body: height 0.36, standoff -0.04, extent -1.799,-1.797 -1.4,-1.403
3D body: height 0.36, standoff -0.04, extent -0.999,-1.797 -0.6,-1.403
3D body: height 0.36, standoff -0.04, extent -0.199,-1.797 0.2,-1.403
3D body: height 0.36, standoff -0.04, extent 0.601,-1.797 1,-1.403
3D body: height 0.36, standoff -0.04, extent 1.401,-1.797 1.8,-1.403
3D body: height 0.36, standoff -0.04, extent -5.799,-1.797 -5.4,-1.403
3D body: height 0.36, standoff -0.04, extent -4.999,-1.797 -4.6,-1.403
3D body: height 0.36, standoff -0.04, extent -4.199,-1.797 -3.8,-1.403
3D body: height 0.36, standoff -0.04, extent -3.399,-1.797 -3,-1.403
3D body: height 0.36, standoff -0.04, extent -2.599,-1.797 -2.2,-1.403
3D body: height 0.36, standoff -0.04, extent 5.401,-0.997 5.8,-0.603
3D body: height 0.36, standoff -0.04, extent 4.601,-0.997 5,-0.603
3D body: height 0.36, standoff -0.04, extent 3.801,-0.997 4.2,-0.603
3D body: height 0.36, standoff -0.04, extent 3.001,-0.997 3.4,-0.603
3D body: height 0.36, standoff -0.04, extent 2.201,-0.997 2.6,-0.603
3D body: height 0.36, standoff -0.04, extent -1.799,-0.997 -1.4,-0.603
3D body: height 0.36, standoff -0.04, extent 1.401,-0.997 1.8,-0.603
3D body: height 0.36, standoff -0.04, extent -5.799,-0.997 -5.4,-0.603
3D body: height 0.36, standoff -0.04, extent -4.999,-0.997 -4.6,-0.603
3D body: height 0.36, standoff -0.04, extent -4.199,-0.997 -3.8,-0.603
3D body: height 0.36, standoff -0.04, extent -3.399,-0.997 -3,-0.603
3D body: height 0.36, standoff -0.04, extent -2.599,-0.997 -2.2,-0.603
3D body: height 0.36, standoff -0.04, extent 5.401,-0.197 5.8,0.197
3D body: height 0.36, standoff -0.04, extent 4.601,-0.197 5,0.197
3D body: height 0.36, standoff -0.04, extent 3.801,-0.197 4.2,0.197
3D body: height 0.36, standoff -0.04, extent 3.001,-0.197 3.4,0.197
3D body: height 0.36, standoff -0.04, extent 2.201,-0.197 2.6,0.197
3D body: height 0.36, standoff -0.04, extent -1.799,-0.197 -1.4,0.197
3D body: height 0.36, standoff -0.04, extent 1.401,-0.197 1.8,0.197
3D body: height 0.36, standoff -0.04, extent -5.799,-0.197 -5.4,0.197
3D body: height 0.36, standoff -0.04, extent -4.999,-0.197 -4.6,0.197
3D body: height 0.36, standoff -0.04, extent -4.199,-0.197 -3.8,0.197
3D body: height 0.36, standoff -0.04, extent -3.399,-0.197 -3,0.197
3D body: height 0.36, standoff -0.04, extent -2.599,-0.197 -2.2,0.197
3D body: height 0.36, standoff -0.04, extent 5.401,0.603 5.8,0.997
3D body: height 0.36, standoff -0.04, extent 4.601,0.603 5,0.997
3D body: height 0.36, standoff -0.04, extent 3.801,0.603 4.2,0.997
3D body: height 0.36, standoff -0.04, extent 3.001,0.603 3.4,0.997
3D body: height 0.36, standoff -0.04, extent 2.201,0.603 2.6,0.997
3D body: height 0.36, standoff -0.04, extent -1.799,0.603 -1.4,0.997
3D body: height 0.36, standoff -0.04, extent 1.401,0.603 1.8,0.997
3D body: height 0.36, standoff -0.04, extent -5.799,0.603 -5.4,0.997
3D body: height 0.36, standoff -0.04, extent -4.999,0.603 -4.6,0.997
3D body: height 0.36, standoff -0.04, extent -4.199,0.603 -3.8,0.997
3D body: height 0.36, standoff -0.04, extent -3.399,0.603 -3,0.997
3D body: height 0.36, standoff -0.04, extent -2.599,0.603 -2.2,0.997
3D body: height 0.36, standoff -0.04, extent 5.401,1.403 5.8,1.797
3D body: height 0.36, standoff -0.04, extent 4.601,1.403 5,1.797
3D body: height 0.36, standoff -0.04, extent 3.801,1.403 4.2,1.797
3D body: height 0.36, standoff -0.04, extent 3.001,1.403 3.4,1.797
3D body: height 0.36, standoff -0.04, extent 2.201,1.403 2.6,1.797
3D body: height 0.36, standoff -0.04, extent -1.799,1.403 -1.4,1.797
3D body: height 0.36, standoff -0.04, extent -0.999,1.403 -0.6,1.797
3D body: height 0.36, standoff -0.04, extent -0.199,1.403 0.2,1.797
3D body: height 0.36, standoff -0.04, extent 0.601,1.403 1,1.797
3D body: height 0.36, standoff -0.04, extent 1.401,1.403 1.8,1.797
3D body: height 0.36, standoff -0.04, extent -5.799,1.403 -5.4,1.797
3D body: height 0.36, standoff -0.04, extent -4.999,1.403 -4.6,1.797
3D body: height 0.36, standoff -0.04, extent -4.199,1.403 -3.8,1.797
3D body: height 0.36, standoff -0.04, extent -3.399,1.403 -3,1.797
3D body: height 0.36, standoff -0.04, extent -2.599,1.403 -2.2,1.797
3D body: height 0.36, standoff -0.04, extent 5.401,2.203 5.8,2.597
3D body: height 0.36, standoff -0.04, extent 4.601,2.203 5,2.597
3D body: height 0.36, standoff -0.04, extent 3.801,2.203 4.2,2.597
3D body: height 0.36, standoff -0.04, extent 3.001,2.203 3.4,2.597
3D body: height 0.36, standoff -0.04, extent 2.201,2.203 2.6,2.597
3D body: height 0.36, standoff -0.04, extent -1.799,2.203 -1.4,2.597
3D body: height 0.36, standoff -0.04, extent -0.999,2.203 -0.6,2.597
3D body: height 0.36, standoff -0.04, extent -0.199,2.203 0.2,2.597
3D body: height 0.36, standoff -0.04, extent 0.601,2.203 1,2.597
3D body: height 0.36, standoff -0.04, extent 1.401,2.203 1.8,2.597
3D body: height 0.36, standoff -0.04, extent -5.799,2.203 -5.4,2.597
3D body: height 0.36, standoff -0.04, extent -4.999,2.203 -4.6,2.597
3D body: height 0.36, standoff -0.04, extent -4.199,2.203 -3.8,2.597
3D body: height 0.36, standoff -0.04, extent -3.399,2.203 -3,2.597
3D body: height 0.36, standoff -0.04, extent -2.599,2.203 -2.2,2.597
3D body: height 0.36, standoff -0.04, extent 5.401,3.003 5.8,3.397
3D body: height 0.36, standoff -0.04, extent 4.601,3.003 5,3.397
3D body: height 0.36, standoff -0.04, extent 3.801,3.003 4.2,3.397
3D body: height 0.36, standoff -0.04, extent 3.001,3.003 3.4,3.397
3D body: height 0.36, standoff -0.04, extent 2.201,3.003 2.6,3.397
3D body: height 0.36, standoff -0.04, extent -1.799,3.003 -1.4,3.397
3D body: height 0.36, standoff -0.04, extent -0.999,3.003 -0.6,3.397
3D body: height 0.36, standoff -0.04, extent -0.199,3.003 0.2,3.397
3D body: height 0.36, standoff -0.04, extent 0.601,3.003 1,3.397
3D body: height 0.36, standoff -0.04, extent 1.401,3.003 1.8,3.397
3D body: height 0.36, standoff -0.04, extent -5.799,3.003 -5.4,3.397
3D body: height 0.36, standoff -0.04, extent -4.999,3.003 -4.6,3.397
3D body: height 0.36, standoff -0.04, extent -4.199,3.003 -3.8,3.397
3D body: height 0.36, standoff -0.04, extent -3.399,3.003 -3,3.397
3D body: height 0.36, standoff -0.04, extent -2.599,3.003 -2.2,3.397
3D body: height 0.36, standoff -0.04, extent 5.401,3.803 5.8,4.197
3D body: height 0.36, standoff -0.04, extent 4.601,3.803 5,4.197
3D body: height 0.36, standoff -0.04, extent 3.801,3.803 4.2,4.197
3D body: height 0.36, standoff -0.04, extent 3.001,3.803 3.4,4.197
3D body: height 0.36, standoff -0.04, extent 2.201,3.803 2.6,4.197
3D body: height 0.36, standoff -0.04, extent -1.799,3.803 -1.4,4.197
3D body: height 0.36, standoff -0.04, extent -0.999,3.803 -0.6,4.197
3D body: height 0.36, standoff -0.04, extent -0.199,3.803 0.2,4.197
3D body: height 0.36, standoff -0.04, extent 0.601,3.803 1,4.197
3D body: height 0.36, standoff -0.04, extent 1.401,3.803 1.8,4.197
3D body: height 0.36, standoff -0.04, extent -5.799,3.803 -5.4,4.197
3D body: height 0.36, standoff -0.04, extent -4.999,3.803 -4.6,4.197
3D body: height 0.36, standoff -0.04, extent -4.199,3.803 -3.8,4.197
3D body: height 0.36, standoff -0.04, extent -3.399,3.803 -3,4.197
3D body: height 0.36, standoff -0.04, extent -2.599,3.803 -2.2,4.197
3D body: height 0.36, standoff -0.04, extent 5.401,4.603 5.8,4.997
3D body: height 0.36, standoff -0.04, extent 4.601,4.603 5,4.997
3D body: height 0.36, standoff -0.04, extent 3.801,4.603 4.2,4.997
3D body: height 0.36, standoff -0.04, extent 3.001,4.603 3.4,4.997
3D body: height 0.36, standoff -0.04, extent 2.201,4.603 2.6,4.997
3D body: height 0.36, standoff -0.04, extent -1.799,4.603 -1.4,4.997
3D body: height 0.36, standoff -0.04, extent -0.999,4.603 -0.6,4.997
3D body: height 0.36, standoff -0.04, extent -0.199,4.603 0.2,4.997
3D body: height 0.36, standoff -0.04, extent 0.601,4.603 1,4.997
3D body: height 0.36, standoff -0.04, extent 1.401,4.603 1.8,4.997
3D body: height 0.36, standoff -0.04, extent -5.799,4.603 -5.4,4.997
3D body: height 0.36, standoff -0.04, extent -4.999,4.603 -4.6,4.997
3D body: height 0.36, standoff -0.04, extent -4.199,4.603 -3.8,4.997
3D body: height 0.36, standoff -0.04, extent -3.399,4.603 -3,4.997
3D body: height 0.36, standoff -0.04, extent -2.599,4.603 -2.2,4.997
3D body: height 0.36, standoff -0.04, extent -2.599,5.403 -2.2,5.797
3D body: height 0.36, standoff -0.04, extent -3.399,5.403 -3,5.797
3D body: height 0.36, standoff -0.04, extent -4.199,5.403 -3.8,5.797
3D body: height 0.36, standoff -0.04, extent -4.999,5.403 -4.6,5.797
3D body: height 0.36, standoff -0.04, extent -5.799,5.403 -5.4,5.797
3D body: height 0.36, standoff -0.04, extent 1.401,5.403 1.8,5.797
3D body: height 0.36, standoff -0.04, extent 0.601,5.403 1,5.797
3D body: height 0.36, standoff -0.04, extent -0.199,5.403 0.2,5.797
3D body: height 0.36, standoff -0.04, extent -0.999,5.403 -0.6,5.797
3D body: height 0.36, standoff -0.04, extent -1.799,5.403 -1.4,5.797
3D body: height 0.36, standoff -0.04, extent 2.201,5.403 2.6,5.797
3D body: height 0.36, standoff -0.04, extent 3.001,5.403 3.4,5.797
3D body: height 0.36, standoff -0.04, extent 3.801,5.403 4.2,5.797
3D body: height 0.36, standoff -0.04, extent 4.601,5.403 5,5.797
3D body: height 1.1, standoff 0.3, extent -6.55,-6.55 6.55,6.55
3D body: height 0.36, standoff -0.04, extent 5.401,5.403 5.8,5.797
3D body: height -1.7, standoff -2, extent -2.4,-2 1.6,0
3D body: height -1.7, standoff -2, extent -2.375,0 1.625,2
3D body: height -1.7, standoff -2, extent -10.238,-7.863 -6.238,-5.863
3D body: height -1.7, standoff -2, extent 5.487,-7.863 9.487,-5.863
3D body: height -1.7, standoff -2, extent 5.487,7.862 9.487,9.862
3D body: height -1.7, standoff -2, extent 5.487,5.862 9.487,7.862
3D body: height -1.7, standoff -2, extent 5.487,-9.863 9.487,-7.863
3D body: height -1.7, standoff -2, extent -10.238,-9.863 -6.238,-7.863
3D body: height -1.7, standoff -2, extent -10.238,7.862 -6.238,9.862
3D body: height -1.7, standoff -2, extent -10.238,5.862 -6.238,7.862
3D body "M5398MF.STEP": height -2, standoff -6, extent -10.262,-9.862 9.463,9.863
